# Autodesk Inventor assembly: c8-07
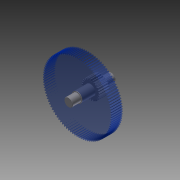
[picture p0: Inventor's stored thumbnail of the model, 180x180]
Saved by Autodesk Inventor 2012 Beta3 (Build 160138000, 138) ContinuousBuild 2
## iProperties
Created: 2010-12
Part Number: c8-07
Document SubType Name: Assembly
Designer: Thom Tremblay
Author: Thom Tremblay
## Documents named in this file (4)
- C:\Inventor 2012 Essentials\Assemblies\Chapter 8\c8-07.iam
- C:\Inventor 2012 Essentials\Assemblies\Chapter 8\Design Accelerators\Shaft c8-07.iam
- C:\Inventor 2012 Essentials\Assemblies\Chapter 8\Design Accelerators\Cut Gear c08-04.iam
- C:\Inventor 2012 Essentials\Assemblies\Chapter 8\Design Accelerators\Spur Gear c98-02.iam
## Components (3 placed, 3 different names)
1. New Shaft:2 [sub-assembly] — Mate:1, Flush:1
2. Cut Gear:1 [sub-assembly]
3. Spur Gear1:1 [sub-assembly] — Mate:1, Flush:1
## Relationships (2: Mate 1, Flush 1)
- Mate:1: New Shaft:2 ↔ Spur Gear1:1
- Flush:1: New Shaft:2 ↔ Spur Gear1:1
